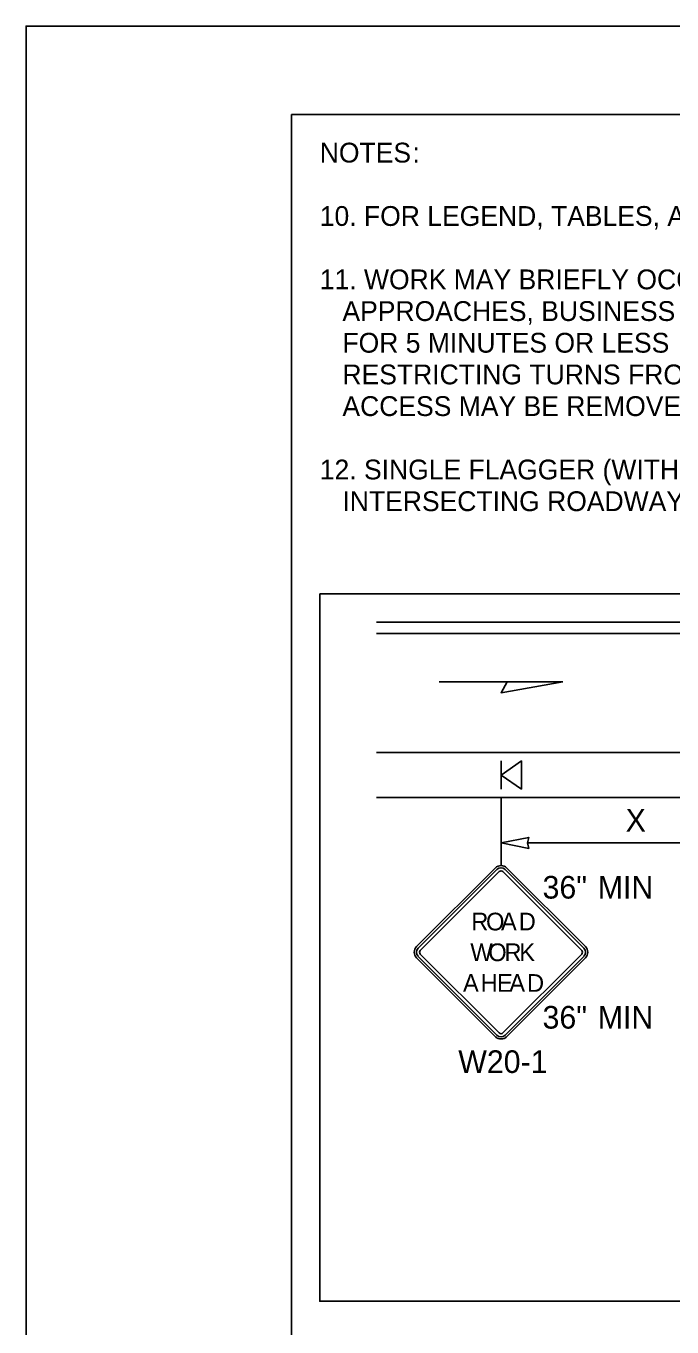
# Model space of a CAD drawing. Extents: x 99999.1 to 100095.7, y 99995 to 100010.7.
# Drawn here: x 100019.062 to 100021.344, y 100006.089 to 100010.687 of the extents above; entities that cross this region are included whole.
import ezdxf

# ---------------------------------------------------------------- set-up
doc = ezdxf.new("R2010")
doc.units = 0
for name, color, linetype in [('RD_ED_ShoulderPavedEdge', 7, 'Continuous'), ('RD_MK_LineDblYellowCenter', 7, 'Continuous'), ('RD_MK_LineEdgeWhite', 7, 'Continuous'), ('SH_GI_GeneralNotesBodyText', 7, 'Continuous'), ('SH_GI_PlotLimits', 7, 'Continuous'), ('SH_GI_SheetBorder', 7, 'Continuous'), ('TR_SN_ConstructionSigns', 7, 'Continuous'), ('TR_WZ_PortableSignMountBlk-Org', 7, 'Continuous'), ('TR_WZ_WorkZoneDetails', 7, 'Continuous'), ('TR_WZ_WorkZoneTextCurrent', 7, 'Continuous')]:
    doc.layers.add(name, color=color, linetype=linetype)

msp = doc.modelspace()

# ---------------------------------------------------------------- linework, layer by layer
at = {"layer": 'RD_ED_ShoulderPavedEdge'}
msp.add_line((100020.3, 100007.9602), (100024.9804, 100007.9602), dxfattribs=at)
at = {"layer": 'RD_MK_LineDblYellowCenter'}
for p, q in [((100020.3, 100008.5802), (100023.7402, 100008.5802)), ((100020.3, 100008.5402), (100023.7402, 100008.5402))]:
    msp.add_line(p, q, dxfattribs=at)
at = {"layer": 'RD_MK_LineEdgeWhite'}
msp.add_line((100020.3, 100008.1202), (100024.9804, 100008.1202), dxfattribs=at)
at = {"layer": 'SH_GI_PlotLimits'}
msp.add_lwpolyline([(100019.0625, 99999.6875), (100036.0625, 99999.6875), (100036.0625, 100010.6875), (100019.0625, 100010.6875)], close=True, dxfattribs=at)
at = {"layer": 'SH_GI_SheetBorder'}
for q in [(100020, 100000), (100035.75, 100010.375)]:
    msp.add_line((100020, 100010.375), q, dxfattribs=at)
at = {"layer": 'TR_SN_ConstructionSigns'}
for p, q in [((100020.7203, 100007.712), (100020.4419, 100007.4336)), ((100020.7258, 100007.7065), (100020.4474, 100007.428)), ((100020.4551, 100007.4203), (100020.7335, 100007.6987)), ((100020.7468, 100007.6987), (100021.0252, 100007.4203)), ((100021.0329, 100007.428), (100020.7545, 100007.7065)), ((100021.0385, 100007.4336), (100020.76, 100007.712)), ((100020.4474, 100007.3993), (100020.7258, 100007.1209)), ((100020.7335, 100007.1286), (100020.4551, 100007.4071)), ((100021.0252, 100007.4071), (100020.7468, 100007.1286)), ((100020.7545, 100007.1209), (100021.0329, 100007.3993)), ((100020.4419, 100007.3938), (100020.7203, 100007.1154)), ((100020.76, 100007.1154), (100021.0385, 100007.3938))]:
    msp.add_line(p, q, dxfattribs=at)
for centre, radius, start, end in [((100020.7402, 100007.6921), 0.0281, 45, 135), ((100020.7402, 100007.6921), 0.0203, 45, 135), ((100020.7402, 100007.6921), 0.00937, 45, 135), ((100020.4617, 100007.4137), 0.0281, 135, 225), ((100020.4617, 100007.4137), 0.0203, 135, 225), ((100020.4617, 100007.4137), 0.00937, 135, 225), ((100021.0186, 100007.4137), 0.00937, 315, 45), ((100021.0186, 100007.4137), 0.0203, 315, 45), ((100021.0186, 100007.4137), 0.0281, 315, 45), ((100020.7402, 100007.1353), 0.0203, 225, 315), ((100020.7402, 100007.1353), 0.00937, 225, 315), ((100020.7402, 100007.1353), 0.0281, 225, 315)]:
    msp.add_arc(centre, radius, start, end, dxfattribs=at)
at = {"layer": 'TR_WZ_PortableSignMountBlk-Org'}
msp.add_line((100020.7402, 100007.9902), (100020.7402, 100008.0902), dxfattribs=at)
msp.add_lwpolyline([(100020.7402, 100008.0401), (100020.812, 100008.0902), (100020.812, 100007.9902)], close=True, dxfattribs=at)
at = {"layer": 'TR_WZ_WorkZoneDetails'}
for p, q in [((100020.7624, 100008.3695), (100020.5213, 100008.3695)), ((100020.7402, 100007.9605), (100020.7402, 100007.7202)), ((100021.5964, 100007.8002), (100020.8339, 100007.8002))]:
    msp.add_line(p, q, dxfattribs=at)
for points in [[(100020.959, 100008.3695), (100020.7402, 100008.3309), (100020.7624, 100008.3695)], [(100020.7402, 100007.8002), (100020.8384, 100007.8195), (100020.8339, 100007.8002), (100020.8384, 100007.781)]]:
    msp.add_lwpolyline(points, close=True, dxfattribs=at)
at = {"layer": 'TR_WZ_WorkZoneTextCurrent'}
msp.add_lwpolyline([(100020.1, 100008.6802), (100025.15, 100008.6802), (100025.15, 100006.1804), (100020.1, 100006.1804)], close=True, dxfattribs=at)

# ---------------------------------------------------------------- texts
at = {"layer": 'SH_GI_GeneralNotesBodyText'}
for s, p in [('NOTES', (100020.1, 100010.205)), (':', (100020.4275, 100010.205)), ('10. FOR LEGEND, TABLES, AND ADDITIONAL NOTES: SEE TC322, SHEET 1.', (100020.1, 100009.981)), ('11. WORK MAY BRIEFLY OCCUR WITHIN LANE CLOSURE ACROSS INTERSECTING ROADWAY ', (100020.1, 100009.757)), ('APPROACHES, BUSINESS ACCESSES, OR DRIVEWAYS. ', (100020.18, 100009.645)), ('FOR 5 MINUTES OR LESS ', (100020.18, 100009.533)), ('RESTRICTING TURNS FROM MAINLINE. CHANNELIZATION DEVICES DELINEATING APPROACH OR ', (100020.18, 100009.421)), ('ACCESS MAY BE REMOVED OR RELOCATED AS NEEDED.', (100020.18, 100009.309)), ('12. SINGLE FLAGGER (WITH RED FLAG/ RED GLOW CONE FLASHLIGHT) MAY BE ADDED TO THE ', (100020.1, 100009.085)), ('INTERSECTING ROADWAY APPROACH TO HELP GUIDE ALTERNATING & TURNING TRAFFIC.', (100020.18, 100008.973))]:
    msp.add_text(s, height=0.07, rotation=360, dxfattribs=at).set_placement(p)
at = {"layer": 'TR_SN_ConstructionSigns'}
for s, p in [('36"', (100020.8869, 100007.6035)), ('MIN', (100021.0819, 100007.6035)), ('36"', (100020.8869, 100007.1439)), ('MIN', (100021.0819, 100007.1439)), ('W20-1', (100020.5892, 100006.9871))]:
    msp.add_text(s, height=0.08, rotation=360, dxfattribs=at).set_placement(p)
for s, p in [('R', (100020.6351, 100007.491)), ('O', (100020.6872, 100007.491)), ('A', (100020.74, 100007.491)), ('D', (100020.8027, 100007.491)), ('W', (100020.6318, 100007.3824)), ('O', (100020.6951, 100007.3824)), ('R', (100020.7523, 100007.3824)), ('K', (100020.8047, 100007.3824)), ('A', (100020.6058, 100007.2739)), ('H', (100020.6683, 100007.2739)), ('E', (100020.7258, 100007.2739)), ('A', (100020.7695, 100007.2739)), ('D', (100020.832, 100007.2739))]:
    msp.add_text(s, height=0.0625, dxfattribs=at).set_placement(p)
at = {"layer": 'TR_WZ_WorkZoneTextCurrent'}
msp.add_text('X', height=0.08, rotation=360, dxfattribs=at).set_placement((100021.1804, 100007.8402))

doc.saveas('drawing.dxf')
